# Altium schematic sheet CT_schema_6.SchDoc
size 287 x 160 mm
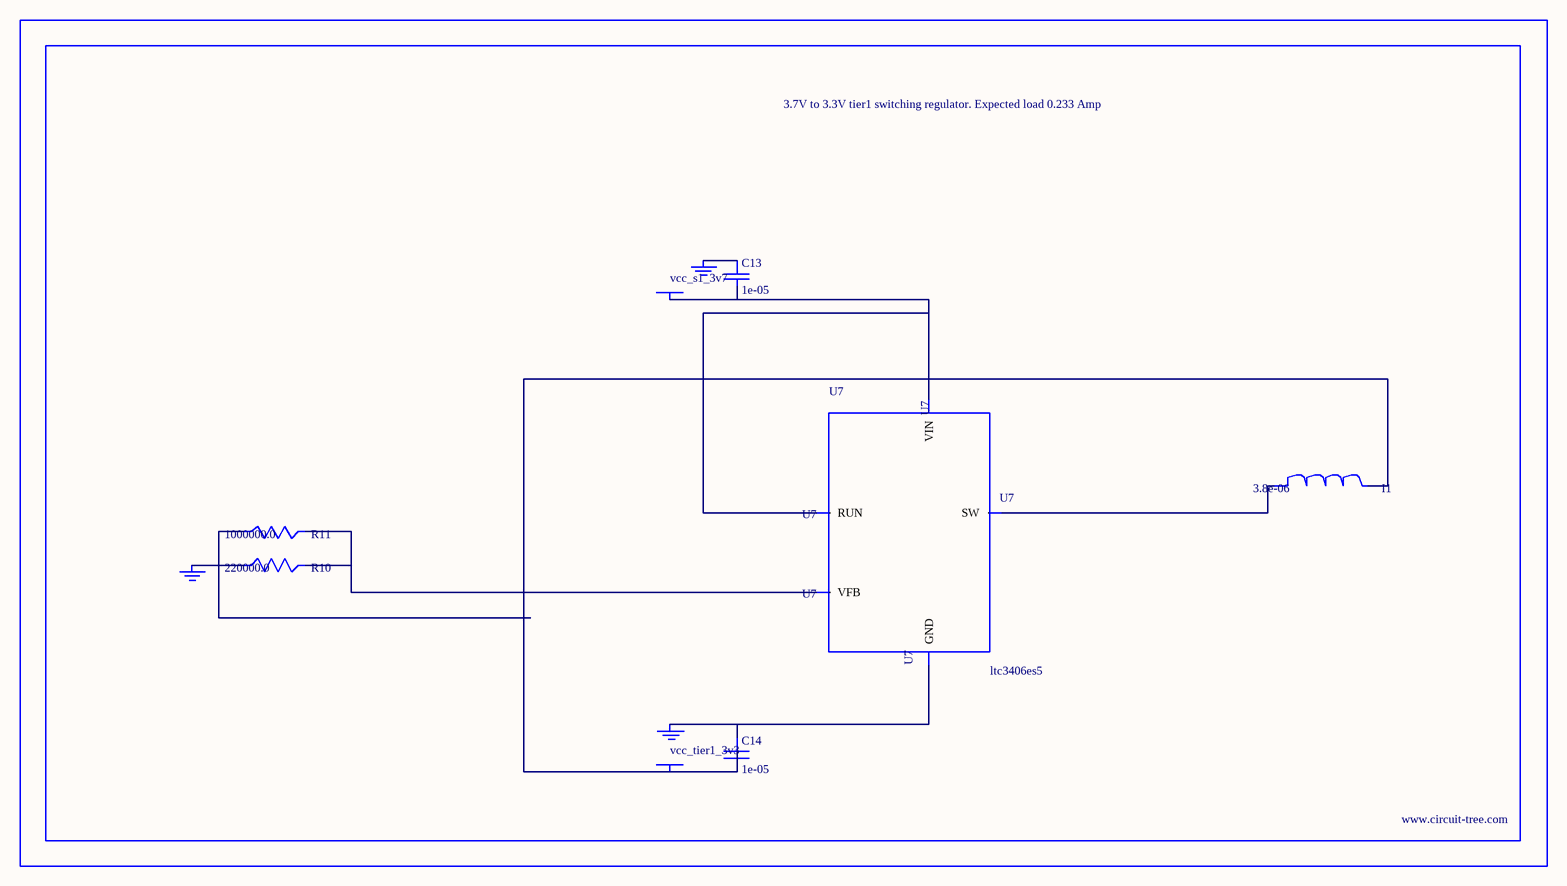
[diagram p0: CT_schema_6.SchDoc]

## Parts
BORDER5  (no value)
C13  1e-05  [C0805]
C14  1e-05  [C0805]
GND_INSTANCE_5_0  (no value)
GND_INSTANCE_5_1  (no value)
GND_INSTANCE_5_2  (no value)
I1  3.8e-06  [DR1040]
POWER_INSTANCE_5_0  vcc_tier1_3v3
POWER_INSTANCE_5_1  vcc_s1_3v7
R10  220000.0  [R0603]
R11  1000000.0  [R0603]
U7  ltc3406es5  [TSOT-23-5]

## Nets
NetC13_1: C13.1 GND_INSTANCE_5_1.0(GND)
NetC13_2: C13.2 POWER_INSTANCE_5_1.0(PWR) U7.1(RUN) U7.4(VIN)
NetC14_1: C14.1 GND_INSTANCE_5_0.0(GND) U7.2(GND)
NetC14_2: C14.2 I1.2 POWER_INSTANCE_5_0.0(PWR) R11.1
NetGND_INSTANCE_5_2_0: GND_INSTANCE_5_2.0(GND) R10.1
NetI1_1: I1.1 U7.3(SW)
NetR10_2: R10.2 R11.2 U7.5(VFB)

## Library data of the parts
BORDER5 = BORDER_PAGE5
C13 C14 = C0805C106K8RACTU
GND_INSTANCE_5_0-GND_INSTANCE_5_2 = GND
I1 = DR1040-3R8-R
POWER_INSTANCE_5_0 POWER_INSTANCE_5_1 = PWR
R10 = RC0603JR-07220KL
R11 = RC0603JR-071ML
